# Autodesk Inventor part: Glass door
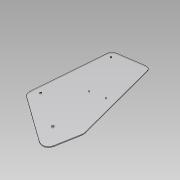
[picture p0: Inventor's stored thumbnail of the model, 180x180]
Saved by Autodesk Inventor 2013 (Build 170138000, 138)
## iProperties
Shininess: 64.0
Length Units: 11269
Angle Units: 11279
Time Units: 11290
Mass Units: 11283
Length Display Precision: 3
Angle Display Precision: 2
Compacted: True
Part Number: Glass door
Document SubType Name: Листовой материал
Created: 2005-02
Material: Polycarbonate, Clear
Designer: =<Author>
Manufacturer: Standard
Standards Organization: Custom
Description: =<Part Number>
Density: 1.2 g/cm^3
Sheet Metal Rule: Default
Mass: 5980.08 g
Surface Area: 12740.7 cm^2
Volume: 4983.4 cm^3
Density: 0.0
Volumn: 0.0
Area: 0.0
PropertySet Name: Model Information
Control State: 0
Master: False
Checked Out: False
Checked Out Date: 2008-10-15
Last Check In Date: 2008-10-15
Author: PVitaliy
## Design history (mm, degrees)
node "Грань1"
feature "УглСкругление1" dims "d44" = 65
body "Solid1"
sketch "Эскиз1"
  geometry: L1 (0, 1005)-(455, 1005); L2 (0, 1005)-(0, 0); L3 (0, 0)-(555, -258); L4 (555, -258)-(630, 15); L5 (630, 15)-(455, 1005); L6 (74, 910)-(74, 86.905); L7 (74, 86.905)-(436.723, -81.713); L8 (476.67, 394.098)-(324.036, 367.117); C1 r 10 at (74, 910); C2 r 10 at (74, 86.905); C3 r 10 at (436.723, -81.713); C4 r 6 at (324.036, 367.117); C5 r 6 at (476.67, 394.098)
  constraints: 16 end point, 5 centre point, 5 coincident, 3 equal radius, 2 parallel, 2 perpendicular, 1 vertical, 1 other
  dimensions: "d33" = 455 distance of L1.start L1.end; "d34" = 1005 distance of L1.start L2.end; "d35" = 630 distance from line of L4.end L2; "d36" = 258 vertical distance of L2.end L3.end; "d37" = 75 horizontal distance of L3.end L4.end; "d38" = 990 distance from line of L4.end L1; "d39" = 74 distance between parallel lines of L6 L2; "d40" = 95 distance from line of L6.start L1; "d41" = 110 distance between parallel lines of L3 L7; "d42" = 400 distance of L6.end L7.end; "d43" = 20 diameter of C1; "d45" = 155 distance of L8.start L8.end; "d46" = 85 distance from line of L5 L8.start; "d47" = 400 distance from line of L4.end L8; "d48" = 12 diameter of C4
feature "Пластина1" dims "Толщина" = 8
other parameters: "Радиус_гибки" = 8 (= Толщина), "Ширина_просечки" = 8 (= Толщина), "Глубина_просечки" = 4 (= 0.5 x Толщина), "Размер_высечки" = 32 (= 4 x Толщина), "Зазор_стыка" = 0.01, "Минимальный_остаток" = 16 (= 2 x Толщина), "Радиус_перехода" = 8 (= Радиус_гибки), "d2" = 8 (= Радиус_гибки), "JacobiRadiusSize" = 8 (= Радиус_гибки), "GapSize" = 8 (= Толщина)
